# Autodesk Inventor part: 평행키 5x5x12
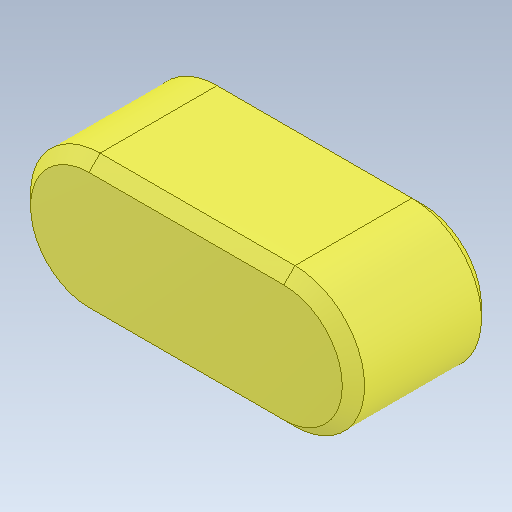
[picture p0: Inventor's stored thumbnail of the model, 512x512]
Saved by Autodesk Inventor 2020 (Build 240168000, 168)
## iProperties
Created: 2024-04
Part Number: 평행키 5x5x12
Material: 강철, 연강
Description: 키 및 해당 키홈
Document SubType Name: Modeling
Designer: oem
Density: 7.85 g/cm^3
Appearance: 기본값
Mass: 2.10816 g
Surface Area: 2.43471 cm^2
Volume: 0.268556 cm^3
Sending System: Autodesk Inventor 2025
Preprocessor: ST-DEVELOPER v20
Author: jhkim
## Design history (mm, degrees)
feature "Solid1"
node "솔리드1"
